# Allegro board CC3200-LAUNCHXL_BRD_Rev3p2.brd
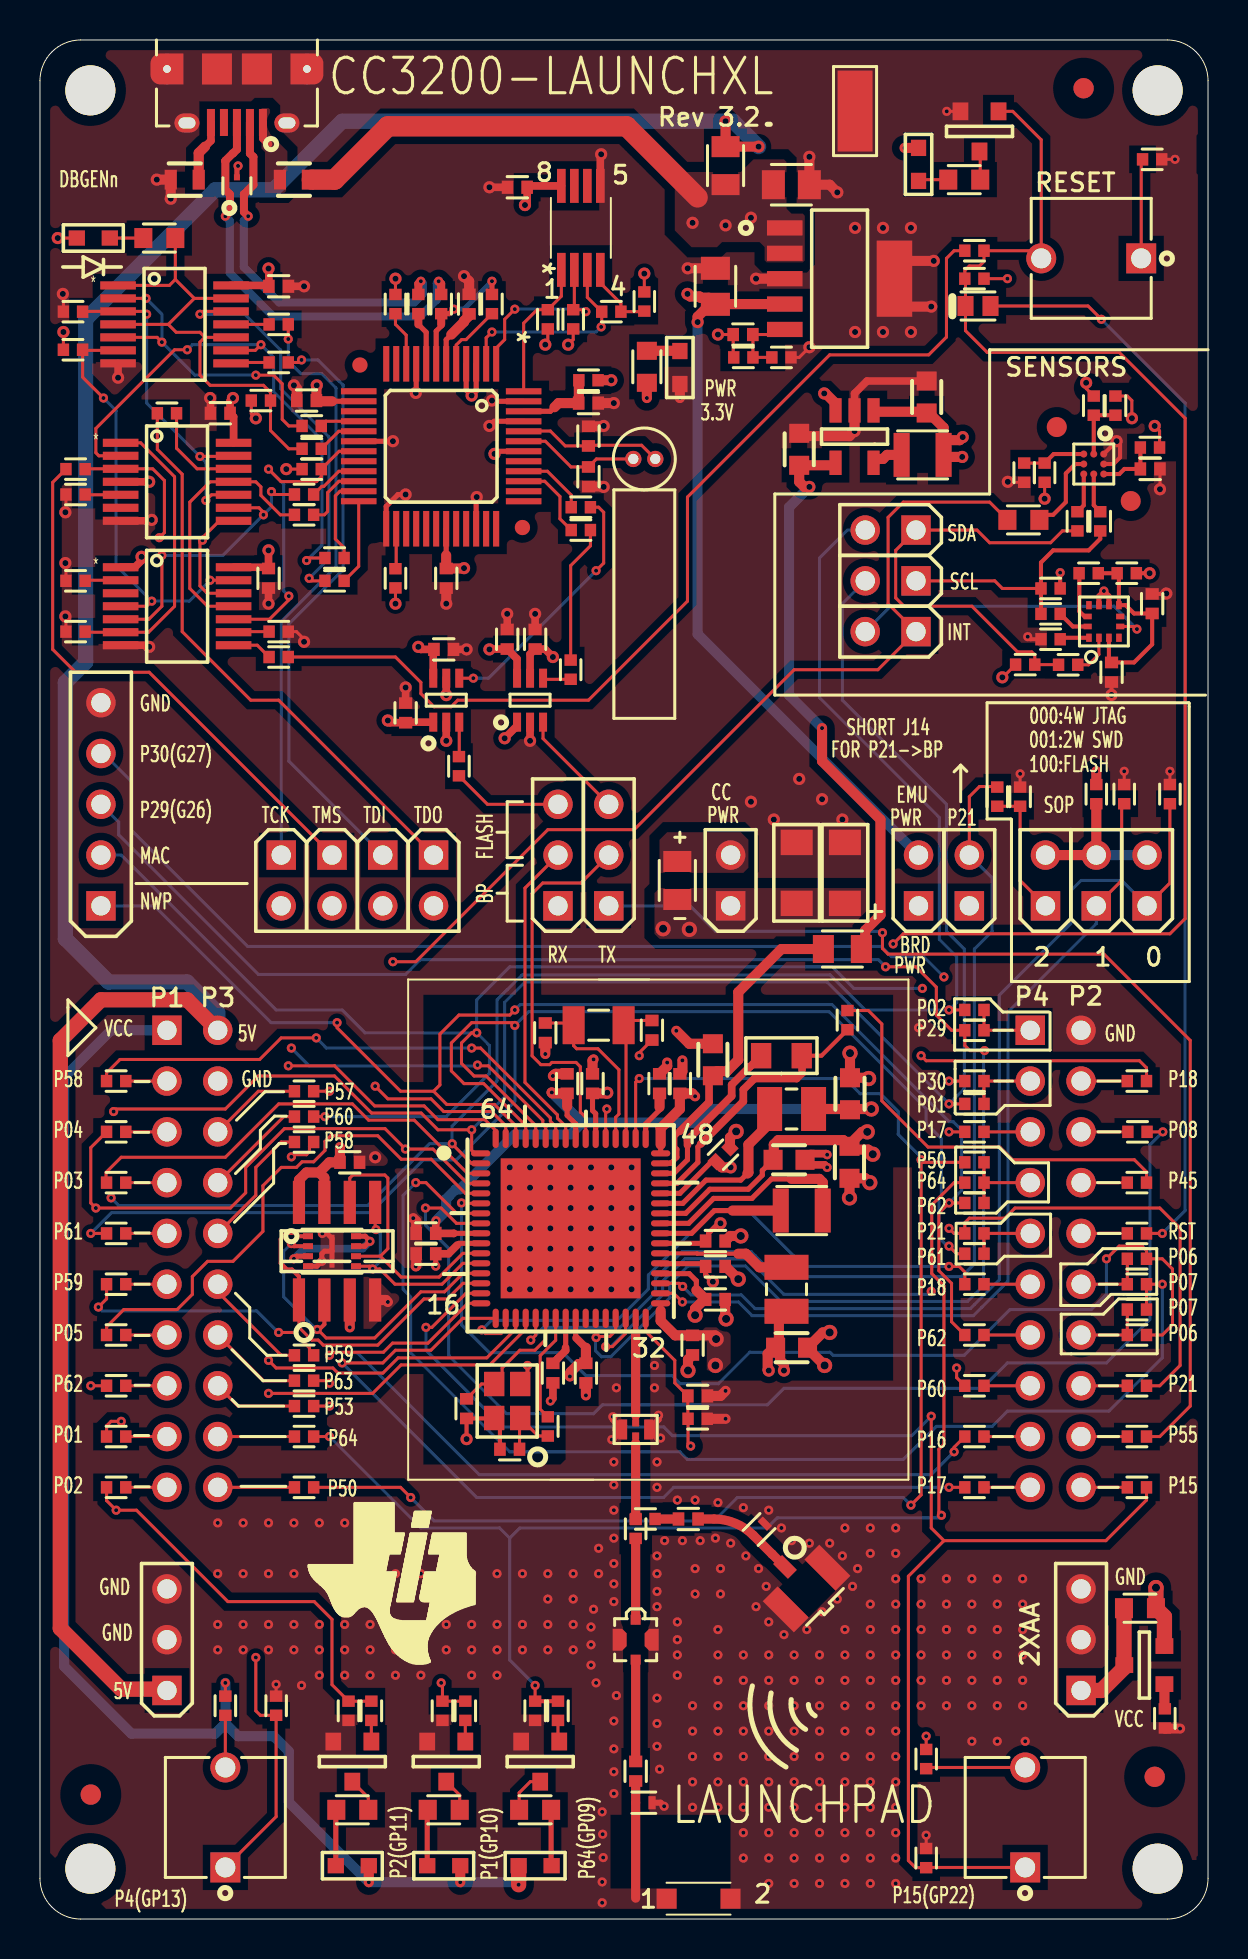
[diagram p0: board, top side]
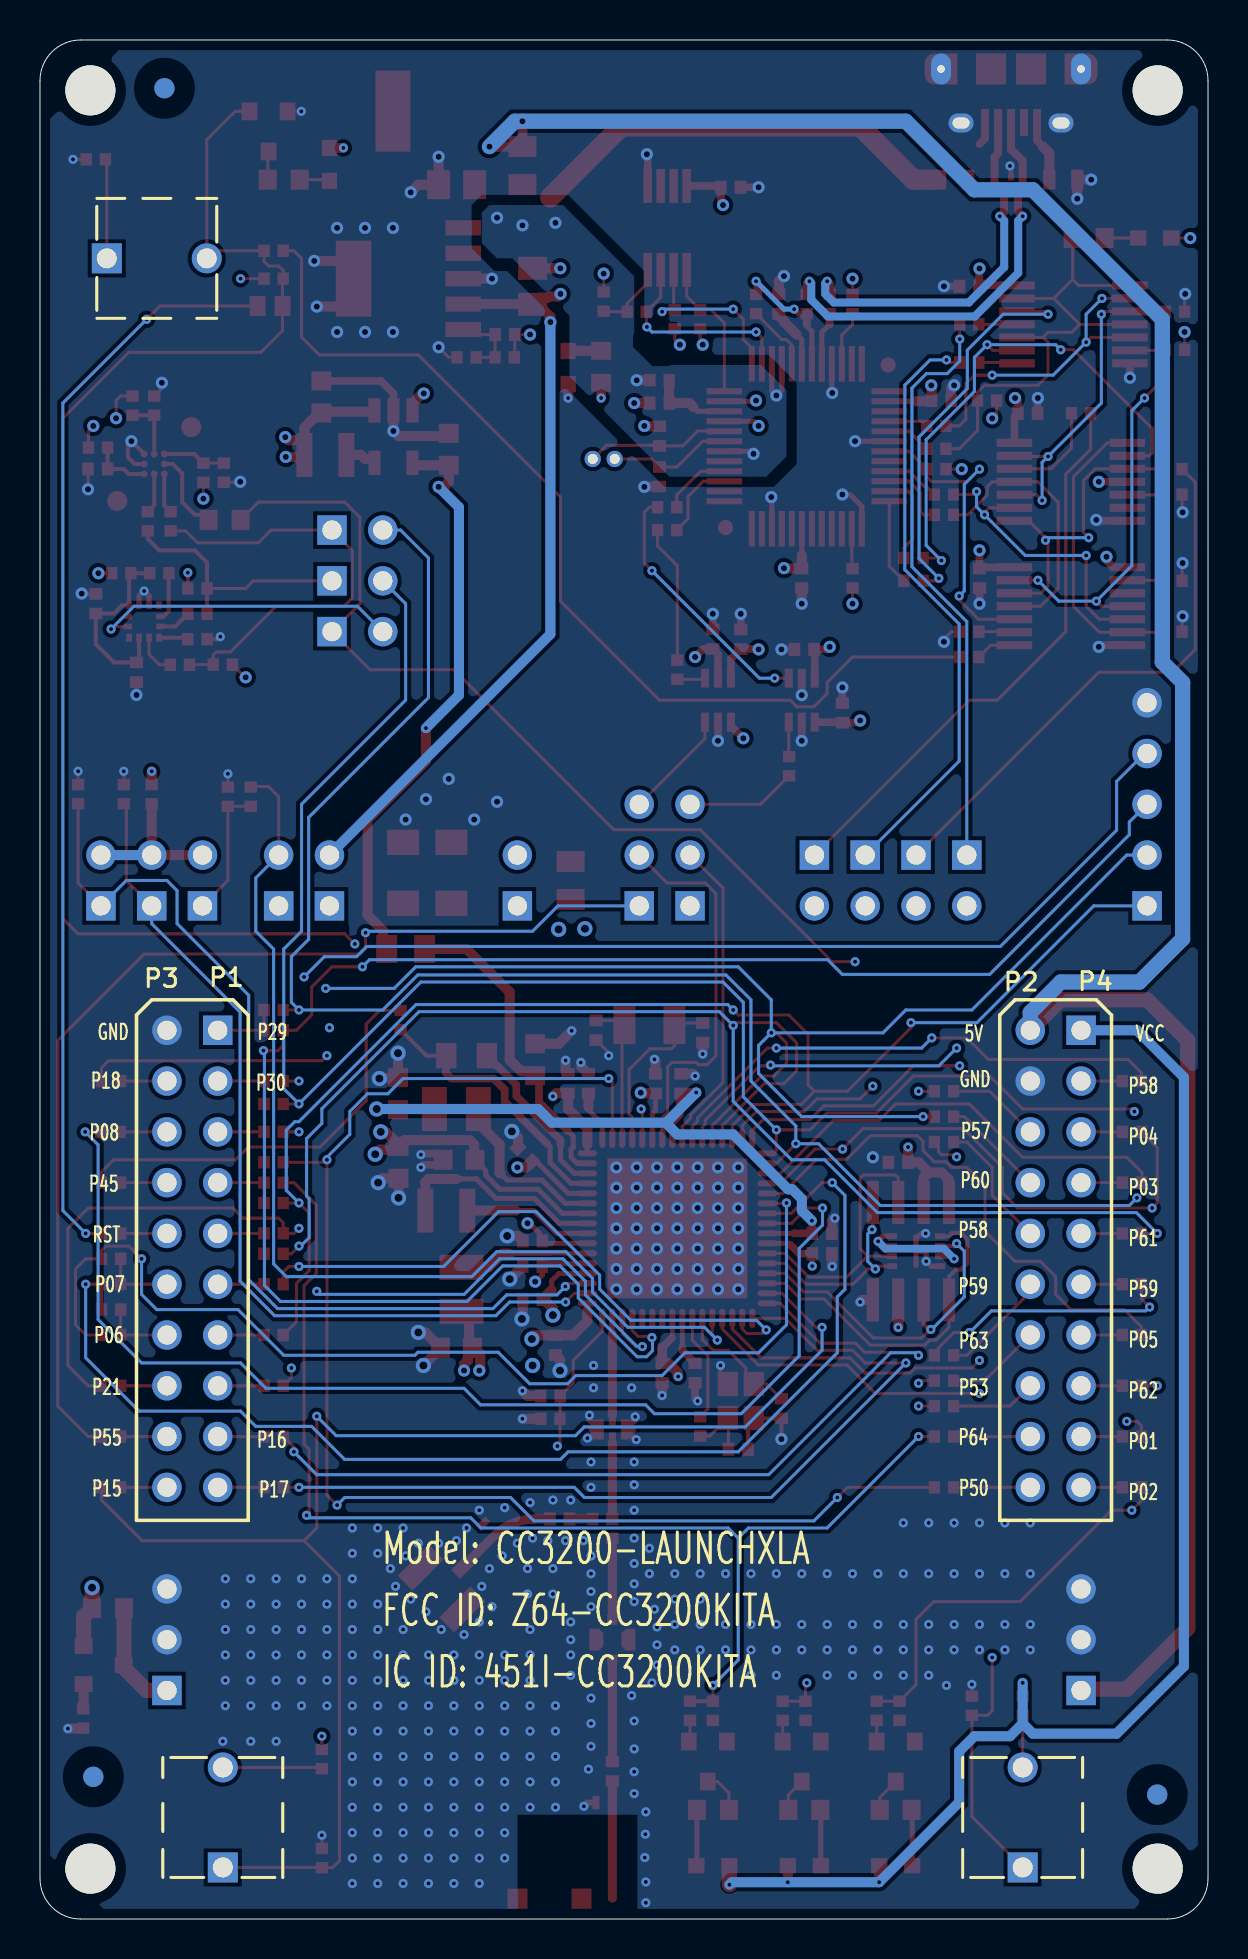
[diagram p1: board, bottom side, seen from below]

Outline 58.42 x 93.98 mm; copper layers: TOP, GND, PWR, BOTTOM. Coordinates in mm from the lower left corner of the outline.
Outline path: 0,91.95 0,2.03 arc(0.6,0.6) 2.03,0 56.39,0 arc(57.82,0.6) 58.42,2.03 58.42,91.95 arc(57.82,93.38) 56.39,93.98 2.03,93.98 arc(0.6,93.38) 0,91.95

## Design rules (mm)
net group DIFFPAIR0: nets N490656 N490660
net group DIFFPAIR1: nets N487558 N497403
net group PWR: nets VCC_MCU_5V

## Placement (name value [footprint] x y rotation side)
C1  10uF  [CC0805]  37.58 86.74 0 top
C2  0.1uF  [CC0402]  23.88 86.61 180 top
C3  0.1uF  [CC0402]  11.94 81.66 0 top
C4  10uF  [CC0805]  33.78 81.66 90 top
C5  33000 pF  [CC0402]  21.46 80.77 90 top
C6  15pF  [CC0402]  35.16 79.25 0 top
C7  0.1uF  [CC0402]  13.34 75.95 180 top
C8  0.1uF  [CC0402]  27.43 75.82 0 top
C9  0.1uF  [CC0402]  9.02 75.31 180 top
C10  27pF  [CC0402]  27.43 74.17 90 top
C11  0.1uF  [CC0402]  55.53 72.53 0 top
C12  27pF  [CC0402]  27.43 72.14 270 top
C13  10uF  [CC0603]  44.35 76.12 90 top
C14  0.1uF  [CC0402]  11.43 67.06 270 top
C15  0.1uF  [CC0402]  20.32 67.06 270 top
C16  10uF  [CC0603]  37.97 73.51 90 top
C17  0.1uF  [CC0402]  55.63 65.79 90 top
C18  0.1uF  [CC0402]  23.37 64.01 90 top
C19  0.1uF  [CC0402]  24.77 64.01 90 top
C20  0.1uF  [CC0402]  20.19 63.5 0 top
C21  0.1uF  [CC0402]  53.59 62.36 270 top
C22  0.1uF  [CC0402]  18.29 60.33 90 top
C23  100uF  [TANT_1206]  37.85 52.32 90 top
C24  100uF  [TANT_1206]  40.26 52.32 90 top
C25  10pF  [CC0402]  30.61 44.45 270 top
C26  10pF  [CC0402]  25.27 44.32 270 top
C27  10uF  [CC0603]  33.66 42.98 90 top
C28  0.1uF  [CC0402]  26.37 41.78 90 top
C29  0.1uF  [CC0402]  27.64 41.78 90 top
C30  0.1uF  [CC0402]  30.99 41.78 90 top
C31  0.1uF  [CC0402]  32 41.78 90 top
C32  10uF  [CC0603]  40.51 41.27 90 top
C33  4.7uF  [CC0402]  34.16 38.23 45 top
C34  22uF  [CC0603]  37.47 37.97 0 top
C35  0.1uF  [CC0402]  15.49 37.85 0 top
C36  22uF  [CC0603]  40.49 37.85 270 top
C37  0.1uF  [CC0402]  19.3 34.29 180 top
C38  4.7uF  [CC0402]  33.78 33.91 0 top
C39  0.1uF  [CC0402]  19.3 33.27 180 top
C40  4.7uF  [CC0402]  33.78 32.64 0 top
C41  0.1uF  [CC0402]  33.78 30.99 0 top
C42  0.1uF  [CC0402]  32.64 28.7 270 top
C43  10uF  [CC0603]  37.59 28.57 0 top
C44  0.1uF  [CC0402]  25.65 27.3 270 top
C45  0.1uF  [CC0402]  27.3 27.3 270 top
C46  0.033uF  [CC0402]  32.89 26.16 0 top
C47  6.2pF  [CC0402]  21.34 25.53 270 top
C48  6.2pF  [CC0402]  23.5 23.5 180 top
C49  10pF  [CC0402]  32.43 20.01 0 top
C50  1.0pF  [INDC_0402CS]  30.2 5.82 180 top
D1  LED  [LED_0603]  43.94 87.76 270 top
D2  LED  [LED_0603]  2.67 84.07 0 top
D3  CD0603-B00340  [DIO_CD0603-S0180R_CUS]  46.91 80.68 180 top
D4  LED  [LED_0603]  32 77.6 270 top
D5  LED  [LED_0603]  15.62 2.67 180 top
D6  LED  [LED_0603]  20.19 2.67 180 top
D7  LED  [LED_0603]  24.77 2.67 0 top
E1  2.45GHz Ant  [ANT_AH316M]  32.94 1.02 0 top
FL1  2.4GHz Filter  [FIL_DEA202450BT-1294C1]  29.79 24.49 0 top
J1  CONN_MICRO_USB  [FCI_10118194-0001]  9.85 92.44 180 top
J2  HEADER_2  [HDR_THVT_1X2_100_M]  43.81 69.47 270 top
J3  HEADER_2  [HDR_THVT_1X2_100_M]  43.81 66.93 270 top
J4  HEADER_2  [HDR_THVT_1X2_100_M]  43.81 64.39 270 top
J5  HEADER_5  [HDR_THVT_1X5_100_M]  3.05 50.67 180 top
J6  HEADER_3  [HDR_THVT_1X3_100_M]  25.91 50.67 180 top
J7  HEADER_3  [HDR_THVT_1X3_100_M]  28.45 50.67 180 top
J8  HEADER_2  [HDR_THVT_1X2_100_M]  12.06 53.21 0 top
J9  HEADER_2  [HDR_THVT_1X2_100_M]  14.61 53.21 0 top
J10  HEADER_2  [HDR_THVT_1X2_100_M]  17.14 53.21 0 top
J11  HEADER_2  [HDR_THVT_1X2_100_M]  19.68 53.21 0 top
J12  HEADER_2  [HDR_THVT_1X2_100_M]  34.54 50.67 180 top
J13  HEADER_2  [HDR_THVT_1X2_100_M]  43.94 50.67 180 top
J14  HEADER_2  [HDR_THVT_1X2_100_M]  46.48 50.67 180 top
J15  HEADER_2  [HDR_THVT_1X2_100_M]  50.29 50.67 180 top
J16  HEADER_2  [HDR_THVT_1X2_100_M]  52.83 50.67 180 top
J17  HEADER_2  [HDR_THVT_1X2_100_M]  55.37 50.67 180 top
J18  CONN_U.FL  [EMERSON_128-0711-201_NEW]  38.34 16.53 225 top
J19  HEADER_3  [HDR_THVT_1X3_100_M]  6.35 11.43 180 top
J20  HEADER_3  [HDR_THVT_1X3_100_M]  52.07 11.43 180 top
J22  CONN_RCPT_10x2  [HDR_THVT_2X10_100_F]  6.35 44.45 180 bottom
J23  CONN_RCPT_10x2  [HDR_THVT_2X10_100_F]  49.53 44.45 180 bottom
J24  RF SWITCH  [CON_RF_MM8030-2600B]  29.79 13.97 0 top
L1  FB  [INDC0603]  7.24 87 0 top
L2  FB  [INDC0603]  12.7 87 0 top
L3  10uH  [IND_CB2518_MM]  44.15 73.23 180 top
L4  10uH  [0805]  37.08 43.18 0 top
L5  2.2uH  [INDC2520X100N_MM]  37.59 40.51 180 top
L6  1uH  [IND_CB2518_MM]  38.1 35.43 180 top
L7  2.2uH  [INDC2520X100N_MM]  37.34 31.5 90 top
L8  5.6nH  [INDC_0402CS]  35.97 19.48 225 top
L9  3.6nH  [CC0402]  29.79 7.39 270 top
NOREF  -  [unnamed]  2.54 6.22 180 top
NOREF#2  -  [unnamed#2]  55.9 91.46 0 top
NOREF#3  -  [unnamed]  52.2 91.57 180 top
NOREF#4  -  [unnamed#2]  2.52 91.46 0 top
NOREF#5  -  [#3]  0 0 90 top
NOREF#6  -  [unnamed]  55.75 7.11 180 top
NOREF#7  -  [unnamed#2]  55.9 2.52 0 top
NOREF#8  -  [unnamed#2]  2.52 2.52 0 top
NOREF#9  -  [#3]  0 93.98 0 top
NOREF#10  -  [unnamed]  2.54 6.22 0 bottom
NOREF#11  -  [unnamed]  55.75 7.11 0 bottom
NOREF#12  -  [unnamed]  52.2 91.57 0 bottom
Q1  BSS138LT3G  [SOT_23_321]  46.99 89.41 180 top
Q2  SI2323DS-T1-GE3  [SOT_23_321]  55.24 12.7 90 top
Q3  BSS138LT3G  [SOT_23_321]  15.62 7.87 180 top
Q4  BSS138LT3G  [SOT_23_321]  20.32 7.87 180 top
Q5  BSS138LT3G  [SOT_23_321]  25.02 7.87 180 top
R1  100R  [RC0402]  55.63 88.01 180 top
R2  0.1 R  [RC0805]  34.29 87.7 90 top
R3  270  [RC0603]  46.23 87 0 top
R4  270  [RC0603]  5.97 84.07 0 top
R5  100k  [RC0402]  46.74 82.04 180 top
R6  10k  [RC0402]  30.23 80.9 270 top
R7  10k  [RC0402]  17.78 80.77 270 top
R8  28  [RC0402]  18.92 80.77 270 top
R9  28  [RC0402]  20.07 80.77 270 top
R10  1.5k  [RC0402]  22.61 80.77 270 top
R11  10k  [RC0402]  1.65 80.39 180 top
R12  2.2K  [RC0402]  28.57 80.39 180 top
R13  10k  [RC0402]  25.4 80.01 90 top
R14  10k  [RC0402]  26.67 80.01 90 top
R15  33  [RC0402]  11.94 79.76 0 top
R16  10k  [RC0402]  1.65 78.49 0 top
R17  51K  [RC0402]  35.18 78.11 180 top
R18  30.1K  [RC0402]  37.08 78.11 180 top
R19  33  [RC0402]  11.94 77.85 0 top
R20  270  [RC0603]  30.35 77.64 90 top
R21  470  [RC0402]  27.43 76.96 0 top
R22  10k  [RC0402]  11.05 75.95 0 top
R23  0 R  [RC0402]  52.7 75.69 270 top
R24  DNP  [RC0402]  53.79 75.69 90 top
R25  33  [RC0402]  6.35 75.31 180 top
R26  33  [RC0402]  13.59 74.68 180 top
R27  0 R  [RC0402]  55.52 73.6 0 top
R28  33  [RC0402]  13.59 73.53 180 top
R29  33  [RC0402]  1.78 72.52 180 top
R30  10k  [RC0402]  13.59 72.52 0 top
R31  DNP  [RC0402]  49.23 72.34 90 top
R32  0 R  [RC0402]  50.25 72.34 270 top
R33  10k  [RC0402]  1.78 71.25 180 top
R34  33  [RC0402]  13.21 71.25 180 top
R35  33  [RC0402]  27.05 70.61 0 top
R36  33  [RC0402]  13.21 70.23 180 top
R37  DNP  [RC0603]  49.19 69.98 180 top
R38  0 R  [RC0402]  51.89 69.91 90 top
R39  0 R  [RC0402]  53.03 69.91 90 top
R40  33  [RC0402]  27.05 69.47 0 top
R41  33  [RC0402]  14.73 68.07 180 top
R42  0 R  [RC0402]  52.45 67.31 180 top
R43  0 R  [RC0402]  54.36 67.31 0 top
R44  10k  [RC0402]  17.78 67.06 90 top
R45  10k  [RC0402]  1.78 66.93 180 top
R46  33  [RC0402]  14.73 66.93 180 top
R47  3.3K  [RC0402]  50.55 66.55 180 top
R48  0 R  [RC0402]  50.55 65.28 0 top
R49  10k  [RC0402]  1.78 64.39 180 top
R50  10k  [RC0402]  11.94 64.39 0 top
R51  0 R  [RC0402]  50.55 64.01 0 top
R52  33  [RC0402]  11.94 63.12 0 top
R53  33  [RC0402]  26.54 62.48 90 top
R54  3.3K  [RC0402]  49.28 62.74 0 top
R55  0 R  [RC0402]  51.42 62.73 0 top
R56  33  [RC0402]  20.95 57.66 90 top
R57  1k  [RC0402]  52.83 56.26 270 top
R58  100k  [RC0402]  54.23 56.26 90 top
R59  100k  [RC0402]  56.52 56.26 90 top
R60  0 R  [RC0402]  47.88 56.13 90 top
R61  10k  [RC0402]  49.02 56.13 90 top
R62  0.1 R  [RC0805]  31.88 51.94 270 top
R63  DNP  [RC0402]  46.74 45.47 0 top
R64  0.1 R  [RC0805]  40.13 48.51 0 top
R65  0 R  [RC0402]  40.39 44.96 90 top
R66  0 R  [RC0402]  46.74 44.45 0 top
R67  0 R  [RC0402]  3.81 41.91 0 top
R68  0 R  [RC0402]  46.74 41.91 0 top
R69  0 R  [RC0402]  54.86 41.91 0 top
R70  0 R  [RC0402]  13.21 41.4 0 top
R71  DNP  [RC0402]  46.74 40.77 0 top
R72  0 R  [RC0402]  13.21 40.13 0 top
R73  0 R  [RC0402]  3.81 39.37 0 top
R74  DNP  [RC0402]  46.74 39.37 0 top
R75  0 R  [RC0402]  54.89 39.37 0 top
R76  DNP  [RC0402]  13.21 38.86 0 top
R77  DNP  [RC0402]  46.74 37.85 0 top
R78  0 R  [RC0402]  3.81 36.83 0 top
R79  DNP  [RC0402]  46.74 36.83 0 top
R80  0 R  [RC0402]  54.86 36.83 0 top
R81  DNP  [RC0402]  46.74 35.81 0 top
R82  0 R  [RC0402]  3.81 34.29 0 top
R83  DNP  [RC0402]  46.74 34.29 0 top
R84  0 R  [RC0402]  54.86 34.29 0 top
R85  DNP  [RC0402]  46.74 33.27 0 top
R86  DNP  [RC0402]  54.86 33.02 0 top
R87  0 R  [RC0402]  3.81 31.75 0 top
R88  DNP  [RC0402]  46.74 31.75 0 top
R89  0 R  [RC0402]  54.86 31.75 0 top
R90  DNP  [RC0402]  54.86 30.48 0 top
R91  0 R  [RC0402]  3.81 29.21 0 top
R92  DNP  [RC0402]  46.74 29.21 0 top
R93  0 R  [RC0402]  54.86 29.21 0 top
R94  DNP  [RC0402]  13.21 28.19 0 top
R95  0 R  [RC0402]  13.21 26.92 0 top
R96  0 R  [RC0402]  3.81 26.67 0 top
R97  DNP  [RC0402]  46.74 26.67 0 top
R98  0 R  [RC0402]  54.86 26.67 0 top
R99  0 R  [RC0402]  13.21 25.65 0 top
R100  3.3M  [RC0402]  32.89 25.02 0 top
R101  0 R  [RC0402]  25.4 24.64 270 top
R102  0 R  [RC0402]  3.81 24.13 0 top
R103  0 R  [RC0402]  13.21 24.13 0 top
R104  0 R  [RC0402]  46.74 24.13 0 top
R105  0 R  [RC0402]  54.86 24.13 0 top
R106  0 R  [RC0402]  3.81 21.59 0 top
R107  0 R  [RC0402]  13.21 21.59 0 top
R108  0 R  [RC0402]  46.74 21.59 0 top
R109  0 R  [RC0402]  54.86 21.59 0 top
R110  DNP  [RC0402]  30.28 20.01 0 top
R111  0 R  [RC0402]  29.79 19.52 270 top
R112  DNP  [RC0603]  55.02 15.54 0 top
R115  0 R  [RC0402]  56.26 10.03 90 top
R116  1k  [RC0402]  9.27 10.67 270 top
R117  10k  [RC0402]  11.81 10.67 90 top
R118  100k  [RC0402]  15.43 10.41 270 top
R119  10k  [RC0402]  16.57 10.41 270 top
R120  100k  [RC0402]  20.13 10.41 270 top
R121  10k  [RC0402]  21.27 10.41 270 top
R122  100k  [RC0402]  24.77 10.41 270 top
R123  10k  [RC0402]  25.91 10.41 270 top
R124  1k  [RC0402]  44.32 8 270 top
R125  270  [RC0603]  15.62 5.46 0 top
R126  270  [RC0603]  20.19 5.46 0 top
R127  270  [RC0603]  24.77 5.46 180 top
R128  10k  [RC0402]  44.32 3.05 90 top
R129  0 R  [RC0402]  46.74 83.44 0 top
SW1  SW TACT  [SW_EVQ-11A05R]  55.08 83.06 180 top
SW2  SW TACT  [SW_EVQ-11A05R]  49.28 2.58 90 top
SW3  SW TACT  [SW_EVQ-11A05R]  9.27 2.58 90 top
TP1  TP_1206  [TP_RCW1206]  40.77 90.42 270 top
U1  TPD2EUSB30  [SOT35P100X50-3N]  9.85 86.69 90 top
U2  93LC46B-I/MS  [TI_MSOP8_0P65_3]  27.05 84.58 0 top
U3  TPS79601  [SOT_223_6_TG]  39.99 81.41 270 top
U4  SN74LVC125APWR  [TSSOP_14_201X177_26]  6.73 79.76 0 top
U5  FT2232D  [QFP_48_284X284_20]  20.07 73.66 180 top
U6  TMP006  [BGA8C50P3X3_153X153X63]  52.7 72.77 270 top
U7  SN74LVC126APWR  [TSSOP_14_201X177_26]  6.86 71.88 0 top
U8  TPS61097-33DBVR  [SOT_23_5]  40.74 74.14 180 top
U9  SN74LVC125APWR  [TSSOP_14_201X177_26]  6.86 65.66 0 top
U10  BMA222  [LGA12R50P4X4_200X200X100]  53.21 64.9 90 top
U11  SN74LVC1T45D  [SOT65P210X110-6N]  20.32 60.96 90 top
U12  SN74LVC1T45D  [SOT65P210X110-6N]  24.51 60.96 90 top
U13  CC3101  [QFN50P900X900_64_PWP_A_EINF]  26.54 34.54 0 top
U14  8M (1M x 8)  [PSON50P300X200X60-9N]  14.61 33.4 0 top
U15  8M (1M x 8)  [SOIC_8_197X157_50]  14.86 33.4 90 top
Y1  CRYSTAL  [XTAL_2P_TH_1P1MMP]  30.78 73.03 180 top
Y2  Crystal  [XTAL_ABS07]  27.94 44.7 180 top
Y3  Crystal  [XTAL_4_SM_104X83X20]  23.37 25.91 90 top

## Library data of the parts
C1 C4-C6 C10 C12 C23-C26 C46-C50 = CAP
C2 C3 C7-C9 C11 C13-C22 C27-C45 = C
D1 D2 D4-D7 = LED
D3 = DIODE
E1 = CHIP_ANTENNA_2T
FL1 = TDK_FILTER_DEA20
J1 = CONN_MICRO_USB_5P_6G
J2-J4 J8-J11 J13-J17 = HEADER_1X2
J5 = HEADER_5
J6 J7 J19 J20 = HEADER_3
J12 = HEADER_2
J18 = CONN_UFL_3P
J22 J23 = CONN_RCPT_0
J24 = CONN_COAX_MURATA_4P
L1 L2 = BEAD_FERRITE
L3-L9 = INDUCTOR
Q1 Q3-Q5 = MOSFET_I_EN_GSD
Q2 = MOSFET_I_EP_GSD
R1-R112 R115-R129 = RESISTOR
SW1-SW3 = SW_TACT_SPST
TP1 = TP_1206
U1 = TPD2EUSB30
U2 = EEPROM-93C46B_4
U3 = TPS79601_SOT-223_0
U4 U9 = SN74LVC125A
U5 = FT2232_LQFP_48P
U6 = TMP006
U7 = SN74LVC126A
U8 = TPS61097-33
U10 = BMA222
U11 U12 = SN74LVC1T45
U13 = CC3101_LP_V2
U14 = FLASH_USON
U15 = FLASH
Y1 Y2 = CRYSTAL
Y3 = CRYSTAL_EPSON_FA20H_4P

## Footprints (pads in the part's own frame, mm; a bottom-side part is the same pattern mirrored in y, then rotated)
0805
  rect 1.016x1.27 smd: 1(-1.016,0) 2(1.016,0)
ANT_AH316M
  rect 1x1 smd: 1(-1.6,0) 2(1.6,0)
BGA8C50P3X3_153X153X63
  round 1 smd: (-1.85,-1.85) (1.85,1.85)
  round 0.35 smd: A1(-0.5,0.5) A2(0,0.5) A3(0.5,0.5) B1(-0.5,0) B3(0.5,0) C1(-0.5,-0.5) C2(0,-0.5) C3(0.5,-0.5)
CC0402
  rect 0.58x0.66 smd: 1(-0.49,0) 2(0.49,0)
CC0603
  rect 0.95x1 smd: 1(-0.8,0) 2(0.8,0)
CC0805
  rect 1.15x1.45 smd: 1(-0.9,0) 2(0.9,0)
CON_RF_MM8030-2600B
  rect 0.5x0.5 smd: 1(0,1) 2(0,-1)
  custom 0.175x0.175 smd: 3(-0.8,0) 4(0.8,0)
DIO_CD0603-S0180R_CUS
  rect 0.8x1 smd: 1(-0.625,0) 2(0.625,0)
EMERSON_128-0711-201_NEW
  rect 0.635x1.05 smd: 1(0,-1.525)
  rect 1.05x2.2 smd: 2A(-1.475,0) 2B(1.475,0)
FCI_10118194-0001
  rect 0.4x1.35 smd: 1(-1.3,2.59) 2(-0.65,2.59) 3(0,2.59) 4(0.65,2.59) 5(1.3,2.59)
  oval 1.25x0.95 hole 0.85x0.55: G1(-2.5,2.615) G2(2.5,2.615)
  custom 0.388x0.388 hole 1.15x0.5: G3(-3.5,-0.085) G6(3.5,-0.085)
  rect 1.5x1.55 smd: G4(-1,-0.085) G5(1,-0.085)
FIL_DEA202450BT-1294C1
  rect 0.35x0.35 smd: 1(0,0.325) 3(0,-0.325)
  rect 0.45x1 smd: 2(0.65,0) 4(-0.65,0)
HDR_THVT_1X2_100_M
  rect 1.473x1.473 hole 0.965: 1(0,0)
  round 1.473 hole 0.965: 2(0,-2.54)
HDR_THVT_1X3_100_M
  rect 1.473x1.473 hole 0.965: 1(0,0)
  round 1.473 hole 0.965: 2(0,-2.54) 3(0,-5.08)
HDR_THVT_1X5_100_M
  rect 1.473x1.473 hole 0.965: 1(0,0)
  round 1.473 hole 0.965: 2(0,-2.54) 3(0,-5.08) 4(0,-7.62) 5(0,-10.16)
HDR_THVT_2X10_100_F
  rect 1.473x1.473 hole 0.965: 1(0,0)
  round 1.473 hole 0.965: 2(-2.54,0) 3(0,-2.54) 4(-2.54,-2.54) 5(0,-5.08) 6(-2.54,-5.08) 7(0,-7.62) 8(-2.54,-7.62) 9(0,-10.16) 10(-2.54,-10.16) 11(0,-12.7) 12(-2.54,-12.7) 13(0,-15.24) 14(-2.54,-15.24) 15(0,-17.78) 16(-2.54,-17.78) 17(0,-20.32) 18(-2.54,-20.32) 19(0,-22.86) 20(-2.54,-22.86)
IND_CB2518_MM
  rect 0.8x2.2 smd: 1(-1.05,0) 2(1.05,0)
INDC0603
  rect 0.61x0.991 smd: 1(-0.7,0) 2(0.7,0)
INDC2520X100N_MM
  rect 1.25x2.2 smd: 1(-1.1,0) 2(1.1,0)
INDC_0402CS
  rect 0.36x0.66 smd: 1(-0.41,0) 2(0.41,0)
LED_0603
  rect 0.813x0.762 smd: 1(-0.826,0) 2(0.826,0)
LGA12R50P4X4_200X200X100
  rect 0.41x0.28 smd: 1(-0.815,0.75) 2(-0.815,0.25) 3(-0.815,-0.25) 4(-0.815,-0.75) 7(0.815,-0.75) 8(0.815,-0.25) 9(0.815,0.25) 10(0.815,0.75)
  rect 0.28x0.41 smd: 5(-0.25,-0.815) 6(0.25,-0.815) 11(0.25,0.815) 12(-0.25,0.815)
PSON50P300X200X60-9N
  rect 0.5x0.3 smd: 1(-1.2,0.75) 2(-1.2,0.25) 3(-1.2,-0.25) 4(-1.2,-0.75) 5(1.2,-0.75) 6(1.2,-0.25) 7(1.2,0.25) 8(1.2,0.75)
  rect 0.25x1.65 smd: 9(0,0)
QFN50P900X900_64_PWP_A_EINF
  oval 0.965x0.305 smd: 1(-4.5,3.75) 2(-4.5,3.25) 3(-4.5,2.75) 4(-4.5,2.25) 5(-4.5,1.75) 6(-4.5,1.25) 7(-4.5,0.75) 8(-4.5,0.25) 9(-4.5,-0.25) 10(-4.5,-0.75) 11(-4.5,-1.25) 12(-4.5,-1.75) 13(-4.5,-2.25) 14(-4.5,-2.75) 15(-4.5,-3.25) 16(-4.5,-3.75) 33(4.5,-3.75) 34(4.5,-3.25) 35(4.5,-2.75) 36(4.5,-2.25) 37(4.5,-1.75) 38(4.5,-1.25) 39(4.5,-0.75) 40(4.5,-0.25) 41(4.5,0.25) 42(4.5,0.75) 43(4.5,1.25) 44(4.5,1.75) 45(4.5,2.25) 46(4.5,2.75) 47(4.5,3.25) 48(4.5,3.75)
  oval 0.305x0.965 smd: 17(-3.75,-4.5) 18(-3.25,-4.5) 19(-2.75,-4.5) 20(-2.25,-4.5) 21(-1.75,-4.5) 22(-1.25,-4.5) 23(-0.75,-4.5) 24(-0.25,-4.5) 25(0.25,-4.5) 26(0.75,-4.5) 27(1.25,-4.5) 28(1.75,-4.5) 29(2.25,-4.5) 30(2.75,-4.5) 31(3.25,-4.5) 32(3.75,-4.5) 49(3.75,4.5) 50(3.25,4.5) 51(2.75,4.5) 52(2.25,4.5) 53(1.75,4.5) 54(1.25,4.5) 55(0.75,4.5) 56(0.25,4.5) 57(-0.25,4.5) 58(-0.75,4.5) 59(-1.25,4.5) 60(-1.75,4.5) 61(-2.25,4.5) 62(-2.75,4.5) 63(-3.25,4.5) 64(-3.75,4.5)
  rect 7x7 smd: 65(0,0)
QFP_48_284X284_20
  round 0.762 smd: (-4.064,4.064) (4.064,-4.064)
  rect 0.305x1.778 smd: 1(-2.75,-4.125) 2(-2.25,-4.125) 3(-1.75,-4.125) 4(-1.25,-4.125) 5(-0.751,-4.125) 6(-0.251,-4.125) 7(0.249,-4.125) 8(0.749,-4.125) 9(1.249,-4.125) 10(1.749,-4.125) 11(2.249,-4.125) 12(2.749,-4.125) 25(2.75,4.125) 26(2.25,4.125) 27(1.75,4.125) 28(1.25,4.125) 29(0.751,4.125) 30(0.251,4.125) 31(-0.249,4.125) 32(-0.749,4.125) 33(-1.249,4.125) 34(-1.749,4.125) 35(-2.249,4.125) 36(-2.749,4.125)
  rect 1.778x0.305 smd: 13(4.125,-2.75) 14(4.125,-2.25) 15(4.125,-1.75) 16(4.125,-1.25) 17(4.125,-0.751) 18(4.125,-0.251) 19(4.125,0.249) 20(4.125,0.749) 21(4.125,1.249) 22(4.125,1.749) 23(4.125,2.249) 24(4.125,2.749) 37(-4.125,2.75) 38(-4.125,2.25) 39(-4.125,1.75) 40(-4.125,1.25) 41(-4.125,0.751) 42(-4.125,0.251) 43(-4.125,-0.249) 44(-4.125,-0.749) 45(-4.125,-1.249) 46(-4.125,-1.749) 47(-4.125,-2.249) 48(-4.125,-2.749)
RC0402
  rect 0.57x0.62 smd: 1(-0.48,0) 2(0.48,0)
RC0603
  rect 0.9x1 smd: 1(-0.8,0) 2(0.8,0)
RC0805
  rect 1.05x1.4 smd: 1(-0.95,0) 2(0.95,0)
SOIC_8_197X157_50
  rect 2.159x0.61 smd: 1(-2.44,1.905) 2(-2.44,0.635) 3(-2.44,-0.635) 4(-2.44,-1.905) 5(2.44,-1.905) 6(2.44,-0.635) 7(2.44,0.635) 8(2.44,1.905)
SOT35P100X50-3N
  rect 0.3x0.3 smd: 1(-0.425,0.35) 2(-0.425,-0.35) 3(0.425,0)
SOT65P210X110-6N
  rect 0.95x0.4 smd: 1(-1.1,0.65) 2(-1.1,0) 3(-1.1,-0.65) 4(1.1,-0.65) 5(1.1,0) 6(1.1,0.65)
SOT_23_5
  rect 0.61x1.219 smd: 1(-0.95,-1.31) 2(0,-1.31) 3(0.95,-1.31) 4(0.95,1.31) 5(-0.95,1.31)
SOT_23_321
  rect 0.787x0.889 smd: 1(-0.953,-1.003) 2(0.953,-1.003) 3(0,1.003)
SOT_223_6_TG
  rect 0.762x1.778 smd: 1(-3.175,-2.743) 2(-1.905,-2.743) 3(-0.635,-2.743) 4(0.635,-2.743) 5(1.905,-2.743)
  rect 3.81x1.778 smd: 6(-0.635,2.743)
SW_EVQ-11A05R
  rect 1.5x1.5 hole 1: 1(0,0)
  round 1.5 hole 1: 2(5,0)
TANT_1206
  rect 1.27x1.6 smd: 1(-1.524,0) 2(1.524,0)
TI_MSOP8_0P65_3
  rect 0.432x1.7 smd: 1(-0.975,-2.1) 2(-0.325,-2.1) 3(0.325,-2.1) 4(0.975,-2.1) 5(0.975,2.1) 6(0.325,2.1) 7(-0.325,2.1) 8(-0.975,2.1)
TP_RCW1206
  rect 4.05x1.75 smd: 1(0,0)
TSSOP_14_201X177_26
  rect 1.778x0.406 smd: 1(-2.825,1.95) 2(-2.825,1.3) 3(-2.825,0.65) 4(-2.825,0) 5(-2.825,-0.65) 6(-2.825,-1.3) 7(-2.825,-1.95) 8(2.825,-1.95) 9(2.825,-1.3) 10(2.825,-0.65) 11(2.825,0) 12(2.825,0.65) 13(2.825,1.3) 14(2.825,1.95)
unnamed
  round 1.016 smd: 1(0,0)
unnamed#2
  round 2.5 hole 2.5 unplated: (0,0)
XTAL_2P_TH_1P1MMP
  round 0.813 hole 0.508: 1(0,0) 2(1.1,0)
XTAL_4_SM_104X83X20
  rect 1.219x1.016 smd: 1(-0.85,-0.65) 2(0.85,-0.65) 3(0.85,0.65) 4(-0.85,0.65)
XTAL_ABS07
  rect 1.1x1.9 smd: 1(-1.25,0) 2(1.25,0)

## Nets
GND: C1.2 C2.2 C3.2 C4.2 C5.2 C7.2 C8.2 C9.2 C10.2 C11.2 C12.2 C13.2 C14.2 C15.2 C16.2 C17.2 C18.2 C19.2 C20.2 C21.2 C22.2 C23.2 C24.2 C25.2 C26.2 C27.2 C28.2 C29.2 C30.2 C31.2 C32.2 C33.2 C34.2 C35.2 C36.2 C37.2 C38.2 C39.2 C40.2 C41.2 C42.2 C43.2 C44.2 C45.2 C46.2 C47.2 C48.2 C50.1 C50.2 D4.2(CATHODE) E1.1(FEED) E1.2 FL1.2(GND1) FL1.4(GND2) J1.G1 J1.G2 J1.G3 J1.G4 J1.G5 J1.G6 J5.5 J18.2A(GND1) J18.2B(GND2) J19.2 J19.3 J20.2 J20.3 J22.4 J23.2 J24.3(GND1) J24.4(GND2) L1.1(Z1) L8.1 L9.2 Q1.2(S) Q3.2(S) Q4.2(S) Q5.2(S) R1.1 R11.2 R18.1 R23.1 R31.1 R33.2 R45.2 R49.2 R50.2 R51.1 R58.2 R59.2 R61.2 R100.2 R115.1 R117.2 R118.2 R120.2 R122.2 R128.2 TP1.1 U1.3(GND) U2.5(GND) U3.3(GND) U3.6(TAB) U4.7(GND) U5.9(GND#9) U5.18(GND#18) U5.25(GND#25) U5.34(GND#34) U5.45(AGND) U5.47(TEST) U6.A1(DGND) U6.A2(AGND) U7.7(GND) U8.2(GND) U9.7(GND) U10.8(GNDIO) U10.9(GND) U11.2(GND) U11.5(DIR) U12.2(GND) U13.65(GND_TAB) U14.4(GND) U14.9(TAB) U15.4(GND) Y3.2 Y3.4
VBAT_CC: C23.1 C24.1 C29.1 C33.1 C35.1 C38.1 C39.1 C40.1 J12.1 R62.2 U13.10(VIN_IO1) U13.37(VIN_DCDC_ANA) U13.39(VIN_DCDC_PA) U13.44(VIN_DCDC_DIG) U13.54(VIN_IO2) U14.3(W\P\) U14.7(R\E\S\E\T\) U14.8(VCC) U15.3(W\P\) U15.7(R\E\S\E\T\) U15.8(VCC)
VBUS_USB1: C1.1 L2.2(Z2) R2.1 R21.2(B) U3.1(EN) U3.2(IN) U5.3(VCC#3) U5.4(RESET#) U5.42(VCC#42)
VCC_BRD: C13.1 C19.1 C22.1 D1.1(ANODE) D5.1(ANODE) D6.1(ANODE) D7.1(ANODE) J12.2 J13.1 J22.1 L3.1 Q2.2(S) R5.1 R20.1 R24.2 R27.2 R32.2 R43.2 R47.1 R54.1 R57.1 R62.1 R112.2 R116.1 R124.1 U8.1(VIN) U8.3(EN) U11.1(VCCA) U12.1(VCCA) U12.5(DIR)
VCC_DCDC_3V3: C16.1 R64.2 U8.4(OUT)
VCC_LDO_3V3: C2.1 C3.1 C4.1 C6.1 C7.1 C9.1 C14.1 C15.1 C18.1 C20.1 D2.1(ANODE) J13.2 R6.1 R7.1 R13.1 R14.1 R16.1 R17.2 R22.1 R30.1 R44.1 U2.8(VCC) U3.4(OUT) U4.14(VCC) U5.14(VCCIOA) U5.31(VCCIOB) U7.4(EN) U7.14(VCC) U9.1(*) U9.14(VCC) U11.6(VCCB) U12.6(VCCB)
VCC_MCU_5V: J19.1 J22.2 R2.2
VDD_ANA: C31.1 C41.1 C43.1 C45.1 L7.1 U13.25(LDO_IN2) U13.36(LDO_IN1) U13.48(VDD_ANA1)
VDD_DIG_CC: C28.1 C32.1 C37.1 L5.1 U13.9(VDD_DIG1) U13.56(VDD_DIG2)
VDD_FL: C27.1 R64.1 U13.47(VDD_FLASH)
VDD_PA: C34.1 C36.1 C42.1 U13.33(VDD_PA_IN) U13.42(DCDC_PA_OUT)
VDD_PLL: C44.1 U13.24(VDD_PLL)
VDD_RAM: C30.1 U13.49(VDD_RAM)
BRD_JTAG_TCK: J8.1 R15.2(B)
BRD_JTAG_TDI: J10.1 R19.2(B)
BRD_JTAG_TDO: J11.1 R25.2(B)
BRD_JTAG_TMS: J9.1 R29.2(B)
CC_GPIO_00: R77.1 R107.2 U13.50(GPIO_00)
CC_GPIO_01: J7.2 U13.55(GPIO_01)
CC_GPIO_02: J6.2 U13.57(GPIO_02)
CC_GPIO_03: R67.1 R76.2 U13.58(GPIO_03)
CC_GPIO_04: R87.1 R94.2 U13.59(GPIO_04)
CC_GPIO_05: J5.2 R72.2 R97.1 U13.60(GPIO_05)
CC_GPIO_06: R82.1 R85.1 U13.61(GPIO_06)
CC_GPIO_07: J5.1 R81.1 R92.1 R96.1 U13.62(GPIO_07)
CC_GPIO_08: R95.2 U13.63(GPIO_08)
CC_GPIO_09: R79.1 R103.2 R122.1 R123.1 U13.64(GPIO_09)
CC_GPIO_10: J3.2 R71.1 R102.1 R120.1 R121.1 U13.1(GPIO_10)
CC_GPIO_11: J2.2 R63.1 R106.1 R118.1 R119.1 U13.2(GPIO_11)
CC_GPIO_12: R78.1 U13.3(GPIO_12)
CC_GPIO_13: J4.1 R37.2 R73.1 R117.1 SW3.1 U13.4(GPIO_13)
CC_GPIO_14: R91.1 U13.5(GPIO_14)
CC_GPIO_15: R86.2 R93.2 U13.6(GPIO_15)
CC_GPIO_16: R89.2 R90.2 U13.7(GPIO_16)
CC_GPIO_17: R75.2 U13.8(GPIO_17)
CC_GPIO_22: R109.2 R128.1 SW2.1 U13.15(GPIO_22)
CC_GPIO_23: J10.2 R104.1 U13.16(GPIO_23/JTAG_TDI)
CC_GPIO_24: J11.2 R74.1 R108.1 U13.17(GPIO_24/JTAG_TDO)
CC_GPIO_26: J5.3 R66.1 U13.29(GPIO_26)
CC_GPIO_27: J5.4 R68.1 U13.30(GPIO_27)
CC_GPIO_28: R69.2 R88.1 U13.18(GPIO_28)
CC_GPIO_30: R99.2 U13.53(GPIO_30)
CC_GPIO_31: R65.2 R80.2
CC_NRESET: C46.1 D3.2(K) Q1.1(G) R5.2 R100.1 R129.2 SW1.2 U13.32(NRESET)
DBG_RST_N: R30.2 U5.19(ADBUS5) U9.10(*)
DBGENN: R4.2 R22.2 R28.2(B) U4.1(*) U4.4(*) U4.10(*) U4.13(*)
DBGMOD: R26.2(B) U4.2(A) U4.5(A)
FL_SWN: L4.1 U13.46(DCDC_FLASH_SW_N)
FL_SWP: L4.2 R65.1 U13.45(DCDC_FLASH_SW_P)
FT_CS: R34.2(B) U7.9(A) U9.5(A)
FT_DI: R36.2(B) U7.11(Y) U9.11(Y)
FT_DO: R41.2(B) U4.9(A) U7.2(A)
FT_SK: R46.2(B) U4.12(A)
FTDI_RX: R40.2(B) R53.2(B)
FTDI_TX: R35.2(B) U11.4(B)
LP_GPIO_01: J7.1 R105.2
LP_GPIO_02: J6.1 R70.2
LP_GPIO_25: J14.1 R83.1 R98.2
LP_RESET_OUT: D3.1(A) R84.2
PA_SWN: L6.1 U13.41(DCDC_PA_SW_N)
PA_SWP: L6.2 U13.40(DCDC_PA_SW_P)
SENS_I2C_SCL: J3.1 R39.1 R47.2 R48.1
SENS_I2C_SDA: J2.1 R38.1 R54.2 R55.1
SFL_CLK: U13.11(SSPI_CLK) U14.6(CLK) U15.6(CLK)
SFL_CS: U13.14(SSPI_CS) U14.1(C\S\) U15.1(C\S\)
SFL_DIN: U13.13(SSPI_DIN) U14.2(DOUT) U15.2(DOUT)
SFL_DOUT: U13.12(SSPI_DOUT) U14.5(DIN) U15.5(DIN)
SOP0: J17.1 R59.1 U13.35(SOP0)
SOP1: J16.1 R58.1 U13.34(SOP1)
SOP2: J15.1 R60.1 R61.1
SRSTN: R52.2(B) R129.1
N24159: L7.2 U13.38(DCDC_ANA_SW)
N24403: L5.2 U13.43(DCDC_DIG_SW)
N27756: FL1.1(IN) U13.31(RF_BG)
N28553: C25.1 U13.51(RTC_XTAL_P) Y2.1
N28565: C26.1 U13.52(RTC_XTAL_N) Y2.2
N30169: C47.1 U13.22(WLAN_XTALM) Y3.3
N36298: J9.2 U13.20(GPIO_29/JTAG_TMS)
N36324: J8.2 U13.19(GPIO_28/JTAG_TCK)
N49988: J15.2 J16.2 J17.2 R57.2
N54209: J22.3 R67.2
N54213: J22.19 R106.2
N54217: J22.5 R73.2
N54221: J22.7 R78.2
N54244: J22.15 R96.2
N54248: J22.17 R102.2
N141545: C48.1 R101.2 Y3.1
N178690: J14.2 R60.2 U13.21(GPIO_25/SOP2)
N185612: C17.1 C21.1 R42.1 R43.1 U10.3(VDDIO) U10.7(VDD)
N185801: C11.1 R27.1 U6.A3(VCC)
N186121: R51.2 U10.1(SDO/ADD0)
N186159: R42.2 U10.11(PS)
N186206: R48.2 U10.12(SCX)
N186210: R55.2 U10.2(SDX)
N187169: R31.2 R32.1 U6.C1(ADDR0)
N187173: R23.2 R24.1 U6.B1(ADDR1)
N187525: R39.2 U6.B3(SCL)
N187543: R38.2 U6.C3(SDA)
N187584: R37.1 U6.C2(\D\T\R\D\Y\)
N187626: J4.2 U10.5(INT1)
N192685: J22.11 R87.2
N195183: D4.1(ANODE) R20.2
N195451: C6.2 R17.1 R18.2 U3.5(FB)
N197053: R101.1 U13.23(WLAN_XTALP)
N224301: C49.1 R110.2
N224305: C49.2 J18.1(CENTER) L8.2
N224377: FL1.3(OUT) R110.1 R111.1
N224405: J24.1(IN) R111.2
N233208: J22.18 R103.1
N288081: J23.16 R98.1
N288085: J23.14 R90.1 R93.1
N288162: J23.4 R69.1
N288174: J23.10 R84.1
N288178: J23.12 R86.1 R89.1
N288672: J23.3 R68.2 R71.2
N288674: J23.5 R74.2
N288676: J23.7 R77.2 R79.2 R81.2
N288678: J23.9 R83.2 R85.2
N288680: J23.11 R88.2
N288682: J23.13 R92.2
N288684: J23.15 R97.2
N288686: J23.17 R104.2
N288688: J23.19 R108.2
N288796: J23.1 R63.2 R66.2
N292143: J20.1 Q2.3(D) R112.1
N314690: J6.3 R56.1(A)
N329065: Q2.1(G) R115.2
N394921: L3.2 U8.5(L)
N412421: J22.6 R70.1
N412425: J22.8 R72.1
N439074: J23.20 R109.1
N439968: J22.20 R107.1
N454667: J23.8 R80.1
N454954: J22.10 R76.1
N454967: J22.12 R94.1
N466203: J22.9 R82.2
N466207: J22.13 R91.2
N466247: J22.14 R95.1
N466251: J22.16 R99.1
N466300: J23.6 R75.1
N466314: J23.18 R105.1
N474715: J24.2(OUT) L9.1
N487558: R9.2 R10.1(A) U5.7(USBDP)
N487570: C5.1 U5.6(3V3OUT)
N487672: C8.1 R21.1(A) U5.46(AVCC)
N487804: R10.2(B) U5.5(RSTOUT#)
N487824: R44.2 U5.26(SI/WUB)
N487832: R7.2 U5.10(SI/WUA)
N487932: R40.1(A) U5.39(BDBUS1)
N488104: R35.1(A) U5.40(BDBUS0)
N488180: R14.2 U2.2(CLK) U5.1(EESK)
N488188: R13.2 U2.1(CS) U5.48(EECS)
N488454: R46.1(A) U5.24(ADBUS0)
N488458: R41.1(A) U5.23(ADBUS1)
N488478: R6.2 R12.1 U2.4(DOUT)
N488614: R12.2 U2.3(DIN) U5.2(EEDATA)
N488706: C10.1 U5.44(XTOUT) Y1.1
N488714: C12.1 U5.43(XTIN) Y1.2
N489641: R36.1(A) U5.22(ADBUS2)
N489651: R34.1(A) U5.21(ADBUS3)
N490588: J1.1(VCC) L2.1(Z1)
N490592: J1.5(GND) L1.2(Z2)
N490656: J1.2(D-) R8.1 U1.2(D-)
N490660: J1.3(D+) R9.1 U1.1(D+)
N497403: R8.2 U5.8(USBDM)
N507782: R28.1(A) U5.17(ADBUS6)
N507786: R26.1(A) U5.16(ADBUS7)
N508362: R16.2 U4.6(Y) U9.4(*) U9.13(*)
N508615: R11.1 U4.3(Y) U7.10(EN) U7.13(EN)
N509670: R15.1(A) U4.11(Y)
N509674: R19.1(A) U4.8(Y)
N511498: R49.1 U7.1(EN) U9.6(Y)
N512182: R29.1(A) U7.3(Y) U7.8(Y) U9.12(A)
N512199: R25.1(A) U7.12(A)
N517852: R50.1 U9.9(A)
N517913: D2.2(CATHODE) R4.1
N518669: R52.1(A) U9.8(Y)
N519131: R33.1 U7.5(A)
N519138: R45.1 U9.2(A)
N532592: J7.3 U12.3(A)
N532639: R53.1(A) U12.4(B)
N533262: R56.2(B) U11.3(A)
N553084: R124.2 SW2.2
N553120: R116.2 SW3.2
N553666: R1.2 SW1.1
N555301: D1.2(CATHODE) R3.1
N555325: Q1.3(D) R3.2
N555403: D7.2(CATHODE) R127.1
N555427: D5.2(CATHODE) R125.1
N555431: D6.2(CATHODE) R126.1
N555483: Q5.3(D) R127.2
N555487: Q4.3(D) R126.2
N555495: Q3.3(D) R125.2
N555589: Q3.1(G) R119.2
N555601: Q4.1(G) R121.2
N555605: Q5.1(G) R123.2

Pads without a net: J1 4; NOREF 1; NOREF#3 1; NOREF#6 1; NOREF#10 1; NOREF#11 1; NOREF#12 1; U2 6 7; U5 11 12 13 15 20 27 28 29 30 32 33 35 36 37 38 41; U7 6; U9 3; U10 4 6 10; U13 26 27 28

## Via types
v1: diameter 0.457, hole 0.203, TOP to BOTTOM, 433 vias
v2: diameter 0.61, hole 0.305, TOP to BOTTOM, 158 vias
v3: diameter 0.762, hole 0.406, TOP to BOTTOM, 20 vias

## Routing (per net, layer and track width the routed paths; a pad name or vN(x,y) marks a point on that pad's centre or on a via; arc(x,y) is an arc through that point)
GND: length 136.1
  TOP w0.152: v1(29.97,43.18) 29.97,43.33 C25.2 ; R23.1 52.32,76.55 v2(52.32,76.83) ; R31.1 48.43,71.86 v2(48.41,71.88) ; R11.2 1.17,81.25 v2(1.14,81.28) ; Q1.2 v1(45.35,90.41) ; C11.2 v2(56.02,71.51) ; R18.1 37.97,78.11 v2(38.48,78.61) ; R50.2 12.83,64.39 13.21,64.01 v2(13.21,63.88) ; R117.2 v1(11.81,11.73) ; R45.2 1.3,67.79 v2(1.27,67.82) ; R59.2 v1(56.52,57.4) ; R1.1 v1(56.77,88.01) ; R49.2 1.3,65.12 v2(1.27,65.15) ; R128.2 v1(44.32,4.19) ; R58.2 v1(54.23,57.4) ; v2(1.27,70.36) 1.3,70.39 R33.2 ; R61.2 v1(49.02,57.28)
  TOP w0.203: C48.2 23.01,24.77 Y3.4 22.7,25.04 C47.2 v2(21.34,24) ; R51.1 49.53,64.01 v1(49.4,64.14) ; Y3.2 24.38,27.12 v1(24.38,27.69) ; U6.A2 53.69,72.77 54.02,73.1 54.02,73.74 v2(53.85,73.91) U6.A1 ; C21.2 v2(53.59,61.22) ; v2(56.33,66.29) 56.32,66.28 C17.2
  TOP w0.254: v2(22.48,74.68) 22.71,74.91 U5.45 ; U5.9 18.82,76.35 v2(18.8,76.33) ; 13.4,32.65 13.85,32.65 v1(14.1,32.89) 14.1,33.27 14.22,33.4 U14.9 14.61,34.04 14.35,34.29 v1(14.12,34.29) ; U1.3 9.85,87.63 v1(9.91,87.68) ; U10.9 52.96,66.17 v1(53.21,66.42) 53.46,66.17 53.47,65.71 U10.8 ; v2(21.84,71.12) 21.81,71.09 U5.34 ; U5.47 22.64,75.91 v2(22.61,75.95) ; v2(18.29,71.25) 17.91,71.25 17.32,70.66 U5.25 ; U5.18 17.65,73.91 v2(17.65,73.91)
  TOP w0.305: v1(31.22,5.64) 31.04,5.82 C50.1 ; v1(31.04,24.05) 30.87,24.05 FL1.2 30.94,24.98 v1(30.94,25.2) ; v1(28.65,25.12) 28.65,24.98 FL1.4 28.63,23.98 v1(28.6,23.98)
  TOP w0.381: C19.2 v2(24.77,65.28) ; v2(28.07,88.27) 28.03,88.22 U2.5 ; U4.7 v2(3.91,77.09) ; U12.2 v2(24.51,58.93) ; C3.2 v2(13.21,81.66) ; C22.2 v2(18.29,61.59) ; C2.2 v2(22.48,86.61) ; U9.7 5.38,63.71 v2(5.46,63.63) ; FL1.4 28.8,24.49 ; C44.2 25.65,26.04 v1(25.53,25.91) ; v1(39.37,37.59) 39.24,37.72 38.52,37.72 C34.2 38.27,38.01 38.53,38.28 39.32,38.28 v1(39.37,38.23) ; C13.2 41.36,76.92 40.74,76.3 U8.2 ; U7.7 5.54,69.93 v2(5.59,69.98) ; U11.5 v2(20.32,61.21) ; v2(21.34,63.5) C20.2 ; FL1.2 30.78,24.49 ; C9.2 8.53,76.05 v2(8.51,76.07) ; C18.2 v2(23.37,65.28) ; C14.2 v2(11.43,65.79) ; U11.2 v2(20.32,58.93)
  TOP w0.457: L9.2 C50.2 29.79,1.04
  TOP w0.505: C15.2 v2(20.32,65.79) ; v2(5.84,87) L1.1 v2(6.54,86.04) ; C39.2 18.81,32.66 v1(18.8,32.64) ; v1(57.02,9.53) 56.29,9.53 R115.1 ; C4.2 v2(32.4,82.56) ; C40.2 34.29,32.64 v3(34.92,32) ; 16.76,30.96 17.3,30.96 v1(17.4,30.86) ; C10.2 28.18,74.66 v2(28.19,74.68) ; C46.2 34.04,26.16 v1(34.29,26.42) ; R100.2 v1(34.29,25.02) ; v1(32.13,42.94) 32.13,42.4 C31.2 ; v3(34.82,39.39) 34.51,39.08 C33.2 ; v3(41.5,36.83) 41.29,37.05 C36.2 v3(40.49,36.07) ; v2(12.7,76.71) 12.85,76.56 C7.2 ; C42.2 32.41,27.98 v3(32.41,27.43) ; v2(21.21,82.17) 21.46,81.92 C5.2 ; v2(44.58,80.64) 43.31,80.64 42.74,81.22 U3.6 42.74,82.49 43.18,82.93 v2(44.7,82.93) ; v3(34.32,30.01) 34.27,30.06 C41.2 ; U3.3 v2(35.81,82.04) ; v2(28.19,71.63) 28.18,71.65 C12.2 ; v3(35.05,34.16) 34.53,34.16 C38.2 ; v1(18.67,35.05) 18.81,34.91 C37.2 ; v3(39.5,29.34) 39.15,29.34 C43.2 38.39,28.54 v3(39.24,27.69) ; C8.2 v2(28.7,75.82) ; v1(27.3,26.19) C45.2 ; C29.2 27.64,42.94 v1(27.69,42.99) ; v1(31.37,42.84) 31.37,42.65 C30.2 ; v2(38.48,88.14) C1.2 39.5,86.74 v2(39.88,86.36) ; v3(41.44,42.04) 41.4,42.04 41.36,42.08 C32.2 v3(40.51,43.31) ; D4.2 v1(32,76.07) ; C28.2 25.79,42.27 25.71,42.2 25.69,42.2 v1(25.65,42.16) ; U8.2 v2(40.74,74.42) 40.49,74.17 38.11,74.17 C16.2 ; C27.2 32.47,43.78 v1(31.83,44.42) ; v1(25.27,43.26) C26.2
  GND w0.505: v2(29.59,32.51) 29.84,32.77 34.16,32.77 v3(34.92,32) ; v2(29.59,36.58) 29.84,36.32 32,36.32 34.82,39.14 v3(34.82,39.39) ; v3(35.05,34.16) 34.67,33.78 29.84,33.78 v2(29.59,33.53)
  vias: v1(8.89,19.81) v1(8.89,17.27) v1(8.89,14.73) v1(8.89,13.46) v1(10.16,19.81) v1(10.16,17.27) v1(10.16,14.73) v1(10.16,13.46) v1(11.43,19.81) v1(11.43,17.27) v1(11.43,14.73) v1(11.43,13.46) v1(12.7,19.81) v1(12.7,17.27) v1(12.7,14.73) v1(12.7,13.46) v1(13.08,11.68) v1(13.97,19.81) v1(13.97,17.27) v1(13.97,14.73) v1(13.97,13.46) v1(13.97,12.19) v1(15.24,19.81) v1(15.24,17.27) v1(15.24,14.73) v1(15.24,13.46) v1(15.24,12.19) v1(16.51,17.27) v1(16.51,14.73) v1(16.51,13.46) v1(16.51,12.19) v1(17.78,17.27) v1(17.78,14.73) v1(17.78,13.46) v1(17.78,12.19) v1(19.05,17.27) v1(19.05,14.73) v1(19.05,13.46) v1(19.05,12.19) v1(20.32,17.27) v1(20.32,14.73) v1(20.32,13.46) v1(21.59,17.27) v1(21.59,14.73) v1(21.59,13.46) v1(21.59,12.19) v1(22.86,17.27) v1(22.86,14.73) v1(22.86,13.46) v1(22.86,12.19) v1(24.13,17.27) v1(24.13,14.73) v1(24.13,13.46) v1(25.4,17.27) v1(25.4,16) v1(25.4,14.73) v1(25.4,13.46) v1(26.67,17.27) v1(26.67,16) v1(26.67,14.73) v1(26.67,13.46) v1(27.56,14.61) v1(27.56,13.72) v1(27.56,12.7) v1(27.69,15.49) v1(27.81,11.81) v1(27.94,18.54) v1(27.94,17.27) v1(28.12,5.36) v1(28.14,4.24) v1(28.12,1.85) v1(28.12,0.81) v1(28.17,3.07) v1(28.7,22.86) v1(28.7,21.72) v1(28.7,20.45) v1(28.7,19.05) v1(28.7,17.78) v1(28.7,16.76) v1(28.7,15.88) v1(28.7,9.91) v1(28.7,8.51) v1(28.7,7.37) v1(28.7,6.27) v1(28.83,26.57) v1(28.83,11.18) v1(30.73,27.69) v1(30.73,26.57) v1(30.86,22.86) v1(30.86,21.59) v1(30.86,18.16) v1(30.86,17.27) v1(30.86,16.38) v1(30.86,15.62) v1(30.86,11.05) v1(30.86,9.78) v1(30.86,8.64) v1(30.99,7.49) v1(31.24,18.92) v1(31.88,20.95) v1(31.88,14.86) v1(31.88,13.97) v1(31.88,13.21) v1(31.88,12.19) v1(32.13,18.92) v1(32.64,10.67) v1(32.64,9.4) v1(32.64,8.13) v1(32.64,6.86) v1(32.64,5.59) v1(32.77,20.95) v1(32.77,17.53) v1(32.77,16.26) v1(33.02,18.92) v1(33.78,19.05) v1(33.91,20.83) v1(33.91,14.48) v1(33.91,13.21) v1(33.91,11.94) v1(33.91,10.67) v1(33.91,9.4) v1(33.91,8.13) v1(33.91,6.86) v1(33.91,5.59) v1(34.04,17.53) v1(34.04,16.26) v1(34.54,18.8) v1(35.18,20.57) v1(35.18,13.21) v1(35.18,11.94) v1(35.18,10.67) v1(35.18,9.4) v1(35.18,8.13) v1(35.18,6.86) v1(35.18,5.59) v1(35.18,4.32) v1(35.18,3.05) v1(35.31,18.16) v1(35.81,15.62) v1(35.94,17.53) v1(36.32,16.64) v1(36.45,20.45) v1(36.45,14.86) v1(36.45,13.21) v1(36.45,11.94) v1(36.45,10.67) v1(36.45,9.4) v1(36.45,8.13) v1(36.45,6.86) v1(36.45,5.59) v1(36.45,4.32) v1(36.45,3.05) v1(36.45,1.78) v1(37.08,19.56) v1(37.21,14.22) v1(37.59,18.92) v1(37.72,13.21) v1(37.72,11.94) v1(37.72,10.67) v1(37.72,9.4) v1(37.72,8.13) v1(37.72,6.86) v1(37.72,5.59) v1(37.72,4.32) v1(37.72,3.05) v1(37.72,1.78) v1(38.35,14.48) v1(38.48,18.8) v1(38.99,13.21) v1(38.99,11.94) v1(38.99,10.67) v1(38.99,9.4) v1(38.99,8.13) v1(38.99,6.86) v1(38.99,5.59) v1(38.99,4.32) v1(38.99,3.05) v1(38.99,1.78) v1(39.12,15.37) v1(39.5,18.8) v1(39.88,16) v1(40.13,18.16) v1(40.26,19.56) v1(40.26,14.48) v1(40.26,13.21) v1(40.26,11.94) v1(40.26,10.67) v1(40.26,9.4) v1(40.26,8.13) v1(40.26,6.86) v1(40.26,5.59) v1(40.26,4.32) v1(40.26,3.05) v1(40.26,1.78) v1(40.64,16.64) v1(40.89,17.53) v1(41.53,19.56) v1(41.53,18.29) v1(41.53,15.75) v1(41.53,14.48) v1(41.53,13.21) v1(41.53,11.94) v1(41.53,10.67) v1(41.53,9.4) v1(41.53,8.13) v1(41.53,6.86) v1(41.53,5.59) v1(41.53,4.32) v1(41.53,3.05) v1(41.53,1.78) v1(42.8,19.56) v1(42.8,18.29) v1(42.8,17.02) v1(42.8,15.75) v1(42.8,14.48) v1(42.8,13.21) v1(42.8,11.94) v1(42.8,10.67) v1(42.8,9.4) v1(42.8,8.13) v1(42.8,6.86) v1(42.8,5.59) v1(42.8,4.32) v1(42.8,3.05) v1(42.8,1.78) v1(43.94,44.58) v1(44.07,17.02) v1(44.07,15.75) v1(44.07,14.48) v1(44.07,13.21) v1(44.07,11.94) v1(44.07,10.67) v1(45.34,17.02) v1(45.34,15.75) v1(45.34,14.48) v1(45.34,13.21) v1(45.34,11.94) v1(45.34,10.67) v1(46.61,17.02) v1(46.61,15.75) v1(46.61,14.48) v1(46.61,13.21) v1(46.61,11.94) v1(46.61,10.67) v1(46.61,8.89) v1(47.88,17.02) v1(47.88,15.75) v1(47.88,14.48) v1(47.88,13.21) v1(47.88,11.94) v1(47.88,10.67) v1(47.88,8.89) v1(49.15,17.02) v1(49.15,15.75) v1(49.15,14.48) v1(49.15,13.21) v1(49.15,11.94) v1(49.15,10.67) v1(49.28,8.89) v2(16.76,38.1) v2(23.5,37.59) v2(23.5,36.58) v2(23.5,35.56) v2(23.5,34.54) v2(23.5,33.53) v2(23.5,32.51) v2(23.5,31.5) v2(24.51,37.59) v2(24.51,36.58) v2(24.51,35.56) v2(24.51,34.54) v2(24.51,33.53) v2(24.51,32.51) v2(24.51,31.5) v2(25.53,37.59) v2(25.53,36.58) v2(25.53,35.56) v2(25.53,34.54) v2(25.53,33.53) v2(25.53,32.51) v2(25.53,31.5) v2(26.54,37.59) v2(26.54,36.58) v2(26.54,35.56) v2(26.54,34.54) v2(26.54,33.53) v2(26.54,32.51) v2(26.54,31.5) v2(27.56,37.59) v2(27.56,36.58) v2(27.56,35.56) v2(27.56,34.54) v2(27.56,33.53) v2(27.56,32.51) v2(27.56,31.5) v2(28.57,37.59) v2(28.57,36.58) v2(28.57,35.56) v2(28.57,34.54) v2(28.57,33.53) v2(28.57,32.51) v2(28.57,31.5) v2(29.59,37.59) v2(29.59,35.56) v2(29.59,34.54) v2(29.59,31.5) v2(35.56,55.88) v2(36.7,54.99) v2(37.97,57.02) v2(39.12,56.01) v2(40.13,54.99) v2(40.77,84.58) v2(40.77,79.38) v2(42.16,84.58) v2(42.16,79.38) v2(43.56,84.58) v2(43.56,79.38)
VBAT_CC: length 31
  TOP w0.254: 13.4,33.15 12.83,33.15 v1(12.7,33.02) ; 20.87,33.71 20.95,33.79 U13.10 ; v2(34.04,34.8) 33.94,34.8 33.44,34.3 33.44,34.05 C38.1 33.18,33.79 U13.39 ; U13.44 32,36.29 33.59,37.88 C33.1 ; U14.7 16.25,33.65 16.5,33.9 v1(16.5,33.9) 16.5,33.92 16.27,34.15 U14.8 ; v2(33.66,31.88) 33.63,31.88 33.29,32.22 C40.1 33.15,32.78 31.06,32.78 U13.37 ; C39.1 v1(19.79,32.66) ; U13.54 27.79,40.28 27.64,40.44 C29.1
  TOP w0.381: 20.87,33.71 20.44,33.27 C39.1
  TOP w0.505: v2(34.54,37.59) 34.11,37.59 C33.1 ; C29.1 28.34,41.29 v2(28.37,41.33) ; 13.96,37.34 14.22,37.08 U15.7 ; 13.96,37.34 14.47,37.85 C35.1 v1(15,38.61) ; 13.96,37.34 13.33,37.34 12.95,36.97 U15.8 ; v1(15.49,29.59) 15.49,30.96
  BOTTOM w0.381: v1(12.7,33.02) 13.21,33.53 16.14,33.53 v1(16.5,33.9)
  vias: v3(31.17,49.53) v3(32.48,49.5)
VBUS_USB1: length 27.6
  TOP w0.254: U5.42 22.86,73.41 v2(22.73,73.28) ; U5.4 21.32,76.47 v2(21.59,76.2) 21.82,76.43 U5.3
  TOP w0.505: R21.2 v2(28.57,76.96) ; 13.6,87 L2.2
  TOP w1.016: 32.89,86.11 29.34,89.66 17.4,89.66 14.73,87 13.6,87
  vias: v2(32.64,84.84) v2(34.29,84.71) v2(35.56,85.09)
VCC_BRD: length 149.2
  TOP w0.152: R5.1 v1(48.39,82.04) ; R24.2 54.38,76.17 54.61,75.95 54.61,75.07 v2(54.61,75.06) ; R116.1 v1(9.27,11.81) ; R32.2 v2(50.25,71.04) ; R54.1 48.16,62.1 v2(48.13,62.1) ; R124.1 v1(44.32,9.14) ; v2(55.75,74.68) 56,74.43 R27.2
  TOP w0.203: R43.2 v2(55.5,67.31) ; R47.1 v1(51.03,67.34)
  TOP w0.381: U12.5 24.51,63.26 C19.1 25.25,63.52 v2(25.65,63.12) ; v2(17.4,59.94) 17.51,59.84 C22.1 18.31,59.86 U11.1 ; U12.1 23.86,59.67 v2(23.24,59.05)
  TOP w0.505: D5.1 v1(16.45,1.84) ; U8.3 39.79,75.8 39.29,76.3 v2(39.22,76.3) ; 45.2,73.77 L3.1 45.3,73.13 v2(46.13,73.13) ; 45.2,73.77 45.39,73.96 46,73.96 v2(46.15,74.12) ; 45.2,73.77 45.2,74.59 44.46,75.32 C13.1 44.28,75.39 41.76,75.39 U8.1 ; D1.1 v1(43.24,88.58) ; D6.1 v1(21.02,1.84) ; R20.1 v1(30.35,76.07) ; R57.1 v1(52.83,57.4)
  TOP w0.762: D7.1 v1(23.94,1.71) ; Q2.2 56.24,15.12 R112.2 v3(55.82,16.57)
  PWR w0.505: v1(44.32,9.14) 44.96,9.78 54.48,9.78 55.82,11.11 v3(55.82,16.57) 57.4,18.16 57.4,49.66
  BOTTOM w0.505: 9.27,9.78 8.76,9.27 4.57,9.27 1.21,12.64 1.21,42.1 3.56,44.45 J22.1 ; 9.27,9.78 9.91,9.14 11.68,9.14 12.45,8.38 12.45,5.84 v1(16.45,1.84) v1(21.02,1.84) 23.81,1.84 v1(23.94,1.71) ; 9.27,9.78 v1(9.27,11.81)
VCC_DCDC_3V3: length 29.1
  TOP w0.505: v2(38.48,71.63) 38.23,71.63 37.97,71.88 C16.1 39.67,72.71 U8.4 ; v1(39.12,59.56) 39.12,57.91 42.04,54.99 42.04,50.21 41.27,49.45 41.27,48.71 R64.2
  BOTTOM w0.505: v1(39.12,59.56) 37.47,61.21 37.47,70.61 v2(38.48,71.63)
VCC_LDO_3V3: length 71.5
  TOP w0.152: R6.1 v2(30.23,82.3) ; R14.1 26.67,78.99 v2(26.42,78.74) ; v2(25.27,78.74) 25.4,78.87 R13.1 ; v2(10.79,75.06) 10.57,75.28 R22.1 ; R7.1 v2(17.78,82.04) ; R16.1 v2(1.17,79.38) ; R30.1 v2(12.32,72.52) ; v2(33.91,79.25) C6.1 34.67,78.13 R17.2 ; D2.1 v2(0.89,84.07) ; R44.1 v2(17.78,65.79)
  TOP w0.254: 14.61,75.91 U5.14 ; 20.32,68.2 U5.31
  TOP w0.381: U4.14 11.4,81.71 C3.1 11.45,82.53 v2(11.43,82.55) ; U7.14 9.68,75.13 C9.1 9.51,75.93 v2(9.65,76.07) ; U9.14 11.37,67.61 C14.1 v2(11.43,68.45) ; v2(22.48,63.5) 22.5,63.52 C18.1 23.86,63.03 U12.6 ; U9.1 4.74,67.61 5.08,67.94 v2(5.08,68.13) ; U11.6 19.67,63.47 C20.1 19.05,63.5 v2(18.92,63.63) ; U7.4 v2(5.46,71.88) ; U2.8 24.43,86.68 C2.1 24.37,85.83 v2(24.26,85.72)
  TOP w0.505: v2(21.21,67.56) 21.19,67.55 C15.1 20.32,67.55 20.32,68.2 ; U3.4 33.79,80.77 C4.1 ; v2(32.38,81.28) 32.51,81.15 32.98,81.15 33.05,81.08 33.46,81.08 C4.1 ; C4.1 33.52,80.76 32.89,80.14 v2(32.89,79.87) ; 14.61,75.91 13.86,75.91 C7.1 13.82,76.69 v2(13.84,76.71)
  BOTTOM w0.505: J13.2 32.89,64.26 v2(32.89,79.87)
VCC_MCU_5V: length 128
  TOP w0.505: v2(34.29,89.92) R2.2 v2(35.94,88.65)
  TOP w0.762: J22.2 7.37,45.97 3.05,45.97 1.02,43.94 1.02,14.54 4.06,11.5 6.28,11.5 J19.1
  BOTTOM w0.762: v2(35.94,88.65) 34.67,89.92 v2(34.29,89.92) 15.11,89.92 11.68,86.49 8.76,86.49 2.29,80.01 2.29,62.87 1.27,61.85 1.27,49.02 3.43,46.86 7.37,46.86 8.89,45.34 J22.2
VDD_ANA: length 16.7
  TOP w0.254: 31.04,38.73 U13.48 ; 32.83,31.45 32.83,31.92 32.47,32.28 31.06,32.28 U13.36 ; U13.25 26.79,29.08 26.81,29.06
  TOP w0.381: 27.3,28.57 26.81,29.06
  TOP w0.505: C43.1 36.96,28.74 36.96,30.02 L7.1 ; C43.1 37.01,28.35 37.01,27.94 37.21,27.74 v2(37.21,27.43) ; C43.1 36.7,28.57 36.4,28.27 36.4,27.48 v2(36.45,27.43) ; 31.04,38.73 31.04,39.55 32,40.51 C31.1 32.62,41.29 v1(32.77,41.15) ; v3(32.77,30.2) 32.77,30.53 33.23,30.99 C41.1 32.83,31.45 ; v1(26.5,27.14) 26.52,27.15 26.52,27.29 26.54,27.32 26.54,27.36 26.94,27.76 27.27,27.76 C45.1 27.3,28.57
VDD_DIG_CC: length 35.6
  TOP w0.254: 26.37,40.64 26.37,40.19 26.79,39.77 U13.56 ; 20.7,34.29 U13.9
  TOP w0.381: v1(19.81,34.92) 19.79,34.91 C37.1 20.7,34.29 20.7,34.29
  TOP w0.505: L5.1 40.47,40.51 C32.1 40.55,40.51 v3(41.58,40.51) ; 26.37,40.64 26.37,41.29 C28.1 25.64,41.29 25.59,41.34 v1(25.6,41.34)
  BOTTOM w0.505: 27.1,39.83 32.82,39.83 33.5,40.51 v3(41.58,40.51) ; 27.1,39.83 27.1,39.8 26.54,39.24 23.75,39.24 21,36.5 20.8,36.5 20.31,36.01 20.31,35.43 v1(19.81,34.92) ; 27.1,39.83 25.6,41.33 v1(25.6,41.34)
VDD_FL: length 16
  TOP w0.254: 32,39.4 31.75,39.14 31.75,38.6 31.86,38.49 31.86,38.09 31.57,37.81 31.51,37.81 31.5,37.79 U13.47
  TOP w0.381: C27.1 33.46,41.99 33.46,40.86 32,39.4
  TOP w0.505: C27.1 33.88,42.4 34.36,42.4 34.92,42.97 34.92,46.35 37.08,48.51 R64.1
VDD_PA: length 18.3
  TOP w0.254: U13.42 32.3,35.29 33.5,36.5 35.42,36.5 36.13,37.21 36.13,37.44 C34.1 ; 31.04,30.42 U13.33
  TOP w0.505: C36.1 40.65,38.48 41.42,38.48 v3(41.65,38.25) ; C36.1 40.49,38.73 41.12,39.37 v3(41.38,39.37) ; C36.1 40.18,38.96 36.92,38.96 36.7,38.73 36.7,38.01 C34.1 ; 31.04,30.42 31.04,29.92 31.77,29.19 C42.1 33.76,29.19 33.76,29.06 v3(33.82,29.01)
  vias: v3(33.78,27.69)
VDD_PLL: length 2.5
  TOP w0.254: U13.24 26.29,28.58 26.29,28.57
  TOP w0.381: 26.29,28.57 26.29,28.43 25.91,28.05 C44.1
VDD_RAM: length 2.5
  TOP w0.254: U13.49 30.29,39.77 30.99,40.46 30.99,40.61
  TOP w0.505: C30.1 30.99,40.61
BRD_JTAG_TCK: length 29.3
  TOP w0.152: R15.2 v1(12.42,79.02)
  BOTTOM w0.152: J8.1 12.06,64.89 14.81,67.64 14.81,76.57 14.09,77.29 13.05,77.29 12.42,77.92 v1(12.42,79.02)
BRD_JTAG_TDI: length 29.9
  TOP w0.152: R19.2 12.95,77.85 v1(13.08,77.98)
  BOTTOM w0.152: v1(13.08,77.98) 13.9,77.98 14.96,76.92 15.16,76.72 15.16,67.49 12.45,64.77 12.45,57.91 J10.1
BRD_JTAG_TDO: length 28.6
  TOP w0.152: R25.2 5.87,73.5 7.11,72.26 7.11,64.39 10.54,60.96 11.94,60.96 J11.1
BRD_JTAG_TMS: length 27.5
  TOP w0.152: J9.1 5.46,62.36 1.78,62.36 0.64,63.5 0.64,71.85 R29.2
CC_GPIO_00: length 70.5
  TOP w0.152: U13.50 29.79,41.86 v1(29.97,42.04) ; v1(43.56,20.7) 44.07,21.21 v1(44.07,37.97) 44.2,37.85 R77.1 ; v1(18.54,21.08) 18.03,21.59 R107.2
  BOTTOM w0.152: v1(43.56,20.7) 43.18,21.08 34.88,21.08 33.71,19.91 19.71,19.91 v1(18.54,21.08) ; v1(29.97,42.04) 40.26,42.04 41.02,41.27 42.04,41.27 42.93,40.39 42.93,39.24 44.07,38.1 v1(44.07,37.97)
CC_GPIO_01: length 19.2
  TOP w0.152: J7.2 27.05,51.82 25.15,51.82 24.61,51.28 24.61,43.17 25.05,42.73 25.49,42.73 25.6,42.84 26.81,42.84 27.03,42.63 27.03,40.36 27.29,40.09 U13.55
CC_GPIO_02: length 15.7
  TOP w0.152: J6.2 24.26,51.56 24.26,41.84 25.88,40.22 25.88,40.05 26.29,39.64 U13.57
CC_GPIO_03: length 34.2
  TOP w0.152: R67.1 3.33,42.32 4,42.99 10.99,42.99 12.06,44.07 v1(13.82,44.07) ; U13.58 25.79,39.64 25.53,39.91 25.53,40.07 22.04,43.56 v1(21.59,43.56) ; R76.2 13.48,38.65 13.48,38.38 13.33,38.23 12.68,38.23 v1(12.57,38.12)
  PWR w0.152: v1(12.57,38.12) 12.57,38.99 13.21,39.62 13.21,41.58 13.82,42.19 v1(13.82,44.07)
  BOTTOM w0.152: v1(13.82,44.07) 14.33,43.56 v1(21.59,43.56)
CC_GPIO_04: length 43.3
  TOP w0.152: v1(21.88,42.71) 21.92,42.67 22.42,42.67 25.15,39.94 25.15,39.75 25.29,39.6 U13.59 ; v1(2.92,30.61) 3.33,31.02 R87.1 ; v1(11.94,29.34) 12.71,29.34 13.48,28.56 13.48,28.4 R94.2
  PWR w0.152: v1(11.94,29.34) 11.3,29.97 11.3,42.29 v1(12.57,43.56)
  BOTTOM w0.152: v1(12.57,43.56) 13.46,42.67 21.84,42.67 v1(21.88,42.71) ; v1(11.94,29.34) 11.91,29.34 10.83,30.42 3.11,30.42 v1(2.92,30.61)
CC_GPIO_05: length 88.7
  TOP w0.152: v1(21.84,44.32) 21.59,44.32 21.08,43.81 21.08,42.79 21.71,42.16 22.31,42.16 24.79,39.68 U13.60 ; R97.1 45.85,27.08 v1(45.85,27.56) ; R72.2 v1(14.25,40.13)
  PWR w0.152: v1(44.13,46.55) 43.18,45.59 43.18,30.23 v1(45.85,27.56)
  BOTTOM w0.152: J5.2 4.06,53.21 11.81,45.47 15.11,45.47 16.26,44.32 v1(21.84,44.32) ; v1(21.84,44.32) 22.48,43.69 22.48,42.29 20.32,40.13 v1(14.25,40.13) ; v1(21.84,44.32) 21.84,45.97 23.5,47.62 39.62,47.62 40.7,46.55 v1(44.13,46.55)
CC_GPIO_06: length 70.4
  TOP w0.152: R82.1 v1(2.54,34.29) ; R85.1 45.85,33.27 v1(45.47,33.66) ; U13.61 24.29,39.68 22.19,41.78 21.21,41.78 20.57,42.42 20.57,43.81 21.59,44.83 23.61,44.83 v1(23.75,44.69)
  BOTTOM w0.152: v1(45.47,33.66) 45.38,33.66 44.96,34.08 44.96,36.02 45.09,36.15 45.09,39.03 44.32,39.79 44.32,40.52 39.46,45.38 24.44,45.38 v1(23.75,44.69) 23.75,40.89 20.83,37.97 19.18,37.97 16.54,35.33 3.58,35.33 v1(2.54,34.29)
CC_GPIO_07: length 96.2
  TOP w0.152: R81.1 v1(45.47,35.81) 44.96,35.31 44.96,32.43 45.59,31.79 45.59,29.87 R92.1 ; U13.62 23.79,39.68 22.73,40.74 20.35,40.74 19.68,41.4 ; 19.68,41.4 18.03,41.4 14.86,44.58 v1(14.86,44.83) ; 19.68,41.4 20,41.72 20,44.26 20.95,45.21 23.5,45.21 v1(23.75,45.47) ; R96.1 v1(2.54,26.67)
  PWR w0.152: J5.1 1.65,49.28 1.65,27.56 v1(2.54,26.67)
  BOTTOM w0.152: v1(45.47,35.81) 46.1,36.45 46.1,39.45 45.68,39.88 45.47,39.88 39.61,45.74 24.02,45.74 v1(23.75,45.47) ; v1(14.86,44.83) 11.56,44.83 5.71,50.67 J5.1
CC_GPIO_08: length 26.2
  TOP w0.152: v1(16.76,41.66) 17.4,41.02 19.56,41.02 20.19,40.39 22.58,40.39 23.29,39.68 U13.63 ; R95.2 14.35,26.92 v1(14.48,26.8)
  PWR w0.152: v1(14.48,26.8) 14.99,26.8 15.75,27.56 15.75,28.32 14.83,29.24 14.83,34.3 14.22,34.91 14.22,38.73 16.76,41.28 v1(16.76,41.66)
CC_GPIO_09: length 94
  TOP w0.152: R79.1 45.72,36.83 44.6,35.71 44.6,32.28 45.21,31.67 45.21,23.75 44.96,23.5 44.96,20.32 v1(45.09,20.19) ; R122.1 v1(24.77,11.68) ; U13.64 22.79,39.44 22.25,39.98 19.9,39.98 19.21,40.67 16.74,40.67 14.73,42.67 v1(12.42,42.67) ; R103.2 v1(14.48,24.13)
  TOP w0.203: R122.1 R123.1
  PWR w0.152: v1(12.42,42.67) 12.32,42.67 11.66,42.01 11.66,30.38 12.7,29.34 12.7,25.91 v1(14.48,24.13)
  BOTTOM w0.152: 23.5,19.05 24,19.56 36.37,19.56 36.87,20.07 44.96,20.07 v1(45.09,20.19) ; 23.5,19.05 22.99,19.56 19.05,19.56 v1(14.48,24.13) ; 23.5,19.05 23.5,12.95 v1(24.77,11.68)
CC_GPIO_10: length 128.7
  TOP w0.152: R121.1 R120.1 20.13,11.75 v1(20.07,11.81) ; R102.1 3.33,24.67 3.56,24.89 v1(4.06,24.89) ; U13.1 21.74,38.29 21.59,38.45 v1(21.59,39.47) 19.91,39.47 19.07,40.31 16.59,40.31 14.73,42.16 10.92,42.16 9.27,40.51 3.81,40.51 v1(3.68,40.39) ; R71.1 v1(45.47,40.77)
  PWR w0.152: v1(20.07,11.81) 20.07,11.89 19.13,12.83 13.72,12.83 13.34,13.21 13.34,17.4 12.83,17.91 8.26,17.91 4.06,22.1 v1(4.06,24.89) 4.32,25.15 4.32,39.75 v1(3.68,40.39)
  BOTTOM w0.152: v1(21.59,39.47) 23.24,41.12 23.24,45.85 24.26,46.86 39.37,46.86 v1(45.47,40.77) 46.23,41.53 46.23,48.51 45.34,49.4 45.34,55.75 40.13,60.96 40.13,65.79 J3.2
CC_GPIO_11: length 117.7
  TOP w0.152: R119.1 R118.1 14.61,11.72 14.61,14.99 13.72,15.88 9.4,15.88 4.83,20.45 v1(3.81,20.45) 3.33,20.93 R106.1 ; U13.2 21.58,37.79 20.62,38.76 v1(20.62,38.78) ; R63.1 v1(45.47,45.47)
  PWR w0.152: v1(3.81,20.45) 3.4,20.85 3.4,25.5 3.94,26.04 3.94,35.69 v1(3.56,36.07)
  BOTTOM w0.152: v1(3.56,36.07) 3.94,35.69 16.39,35.69 19.48,38.78 v1(20.62,38.78) 20.62,39.67 22.86,41.91 22.86,45.97 23.37,46.48 23.37,46.48 24.11,47.22 39.52,47.22 41.27,45.47 v1(45.47,45.47) 45.85,45.85 45.85,48.13 44.98,49 44.98,55.09 38.99,61.09 38.99,68.07 40.39,69.47 J2.2
CC_GPIO_12: length 22.1
  TOP w0.152: R78.1 3.3,36.86 3.3,37.34 4.06,38.1 9.27,38.1 11.94,40.77 15.63,40.77 16.44,39.95 18.72,39.95 21.38,37.29 U13.3
CC_GPIO_13: length 122.8
  TOP w0.152: U13.4 21.37,36.79 19.66,38.51 v1(18.28,38.51) 17.26,39.53 12.22,39.53 10.29,37.59 10.29,36.32 9.52,35.56 v1(2.79,35.56) 2.54,35.81 2.54,38.58 R73.1 ; SW3.1 11.81,5.12 R117.1 11.02,10.19 10.79,10.41 v1(10.79,13.08) ; v1(17.65,47.88) 18.8,47.88 25.4,54.48 29.72,54.48 37.72,62.48 41.91,62.48 J4.1 42.42,65.79 42.42,70.1 43.18,70.87 47.5,70.87 R37.2
  PWR w0.152: v1(10.79,13.08) 10.79,13.55 10.37,13.97 8.93,13.97 8,14.9 8,16.64 6.6,18.03 5.21,18.03 3.05,20.19 3.05,25.65 3.43,26.03 3.43,34.92 v1(2.79,35.56) ; v1(18.28,38.51) 17.65,39.13 v1(17.65,47.88)
CC_GPIO_14: length 26.4
  TOP w0.152: U13.5 21.28,36.29 19.57,38 18.07,38 16.89,39.17 14.54,39.17 14.25,38.89 14.25,38.44 13.69,37.87 13.11,37.87 12.83,37.59 12.06,37.59 11.15,36.68 11.15,34.39 9.65,32.89 8.38,32.89 7.62,32.13 7.62,31.24 6.86,30.48 4.19,30.48 3.33,29.62 R91.1
CC_GPIO_15: length 52.9
  TOP w0.152: v1(21.08,35.81) 21.1,35.79 U13.6 ; R93.2 56.13,29.21 56.64,29.72 56.64,32.51 56.13,33.02 R86.2 55.34,33.43 55.12,33.66 53.98,33.66 v1(53.34,33.02)
  BOTTOM w0.152: v1(21.08,35.81) 21.08,29.72 22.48,28.32 26.16,28.32 27.3,27.18 31.62,27.18 32.03,26.77 33.93,26.77 35.5,28.35 39.52,28.35 39.67,28.19 46.23,28.19 48.51,30.48 52.58,30.48 53.34,31.24 v1(53.34,33.02)
CC_GPIO_16: length 60.5
  TOP w0.152: R90.2 R89.2 v1(56.13,31.75) ; v1(18.8,36.83) 19.3,36.83 20.84,35.29 U13.7
  BOTTOM w0.152: v1(18.8,36.83) 18.16,36.2 18.16,31.5 18.54,31.11 18.54,28.32 23.5,23.37 32,23.37 32.38,22.99 43.18,22.99 44.83,24.64 47.62,24.64 48.39,25.4 53.46,25.4 56.13,28.07 v1(56.13,31.75)
CC_GPIO_17: length 59.6
  TOP w0.152: R75.2 v1(56.16,39.37) ; v1(19.28,35.56) 20.07,35.56 20.83,34.79 U13.8
  BOTTOM w0.152: v1(56.16,39.37) 55.51,38.72 55.51,29.99 53.34,27.81 48.39,27.81 47.12,26.54 37.21,26.54 36.39,25.72 28.13,25.72 27.69,25.27 23.34,25.27 20.45,28.17 20.45,33.54 19.28,34.7 v1(19.28,35.56)
CC_GPIO_22: length 72.9
  TOP w0.152: U13.15 21.3,31.29 19.6,29.59 v1(19.3,29.59) ; 45.21,18.92 53.31,18.92 55.34,20.95 R109.2 ; 45.21,18.92 44.58,19.56 v1(44.58,25.15) ; 45.21,18.92 43.43,17.14 43.43,2.92 43.79,2.57 R128.1 44.33,2.58 SW2.1
  BOTTOM w0.152: v1(44.58,25.15) 43.61,24.18 31.64,24.18 31.2,24.61 23.14,24.61 19.3,28.45 v1(19.3,29.59)
CC_GPIO_23: length 69.6
  TOP w0.152: v1(14.48,28.19) 14.48,28.2 14.63,28.35 17.18,28.35 17.63,28.8 19.41,28.8 21.4,30.79 U13.16 ; R104.1 45.72,23.59 v1(45.72,23.37)
  PWR w0.152: J10.2 17.14,49.14 13.21,45.2 13.21,42.55 12.06,41.4 12.06,30.52 14.39,28.19 v1(14.48,28.19)
  BOTTOM w0.152: v1(14.48,28.19) 14.61,28.32 15.88,28.32 21.97,22.23 44.58,22.23 v1(45.72,23.37)
CC_GPIO_24: length 88.2
  TOP w0.152: U13.17 21.15,30.04 19.55,28.45 17.78,28.45 17.14,27.81 v1(15.11,27.81) ; R108.1 v1(45.47,21.59) ; R74.1 v1(45.47,39.37)
  PWR w0.152: v1(45.47,21.59) 46.48,22.61 46.48,38.35 v1(45.47,39.37) ; J11.2 16,46.99 16,41.02 13.56,38.58 13.56,30.51 14.48,29.59 14.48,29.55 14.48,28.96 15.11,28.32 v1(15.11,27.81)
  BOTTOM w0.152: v1(45.47,21.59) 31.7,21.59 31.19,21.08 21.84,21.08 v1(15.11,27.81)
